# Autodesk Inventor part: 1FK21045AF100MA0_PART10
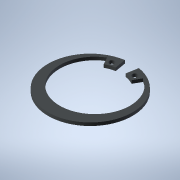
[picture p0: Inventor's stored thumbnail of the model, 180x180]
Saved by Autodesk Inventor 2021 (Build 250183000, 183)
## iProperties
Created: 2025-04
Part Number: 1FK21045AF100MA0_PART10
Material: Generic
Catalog Web Link: www.3dfindit.com
Description: -Servo synchronous motor
Document SubType Name: Modeling
Designer: psAdmin
Mass: 0.642463 g
Surface Area: 12.3927 cm^2
Volume: 0.642463 cm^3
Density: 1 g/cm^3
Appearance: PSOLRGB-212-217-219
Category: PARTsolutions
Title: 1FK21045AF100MA0_PART10
Author: Cadenas PARTsolutions
Comments: Servo synchronous motor
Sending System: PARTsolutions
Preprocessor: ST-DEVELOPER v19.3
PSOL_IDENT_0: {$CADENAS_DATA/23d-libs/siemens_ag/_cat_/52/6b/1fk21045af100ma0.prj},216 {VTYP=3D},{NB=1FK21045AF100
PSOL_IDENT_1: MA0_PART10},{LINA=1FK21045AF100MA0_PART10},{NN=1FK21045AF100MA0_PART10},{NOPRJ=TRUE},{DATE=19.08.202
PSOL_IDENT_2: 5 14:00:38},{GEOMDATE=30.07.2025 02:01:45},{VERSION=},{LINEID=10},{WBVAR=},{WBNUMERIC=}  {NB=1FK2104
PSOL_IDENT_3: 5AF100MA0_PART10},{LINA=1FK21045AF100MA0_PART10},{KT=DUMMY},{PREVIEW=../../../_pool_/cb/72/p_d211_xx
PSOL_IDENT_4: _00434j.png},{DESCSHORT=SIMOTICS S-1FK2 HD, SINAMICS S210 3AC 400V-480V, 2.4 Nm, 3000 rpm},{DESCLONG=
PSOL_IDENT_5: SIMOTICS S-1FK2 HD servo motor M0=2.4 Nm; PN = 0.75 kW at nN=3000 rpm (380-480 V); PN = 0.375 kW at
PSOL_IDENT_6: nN=1500 rpm (200-240 V); with holding brake; degree of protection IP64; cylindrical shaft D19x40mm;
PSOL_IDENT_7: absolute encoder 22-bit + 12-bit multiturn (encoder AM22DQC); with OCC interface; plug size M17, rot
PSOL_IDENT_8: atable; SIMOTICS S-1FK2 servomotorfor a wide range of uses in industrial environments. SIMOTICS S‑1F
PSOL_IDENT_9: K2 servomotors are compact synchronous motors with a high dynamic performance that set themselves ap
PSOL_IDENT_10: art as a result of their high power density, degree of protection and overload capability. The motor
PSOL_IDENT_11: s are available in two variants: as High Dynamic variant (highest dynamic performance as a result of
PSOL_IDENT_12: the low intrinsic moment of inertia for applications demanding a high dynamic performance with low
PSOL_IDENT_13: moved masses) - and as Compact variant (precise and stable closed-loop control for medium up to larg
PSOL_IDENT_14: e moved masses as a result of a medium intrinsic moment of inertia). SIMOTICSS‑1FK2 servomotors full
PSOL_IDENT_15: y exploit their strengths in a system with the SINAMICSS210 frequency converter and simple connectio
PSOL_IDENT_16: n using the one cable connection (OCC). Advantages include the short control and positioning times,
PSOL_IDENT_17: fast and precise correction of disturbing quantities as well as stable control with a high dynamic p
PSOL_IDENT_18: erformance. The servo motors can be configured to address a wide range of requirements. For example
PSOL_IDENT_19: with and without holding brake, IP64 or IP65 degree of protection, singleturn or multiturn absolute
PSOL_IDENT_20: encoders - to name just a few. Further, the servomotors are available in different shaft heights ext
PSOL_IDENT_21: ending from 20 to 100. A shaft sealing ring is available to achieve an IP65 degree of protection and
PSOL_IDENT_22: for subsequent mounting at the motor or as spare part. SIMOTICS - the optimum motor for each and ev
PSOL_IDENT_23: ery motion control application.},{INTNO=804766906411},{SUPPLIERALTNO=1FK2104-5AF10-0MA0},{MANUID=1FK
PSOL_IDENT_24: 21045AF100MA0},{MANUNAME=Siemens},{MANUTYPEDESC=Synchronous motor 1FK2-HD 2.4 NM},{AAU732=SIMOTICS},
PSOL_IDENT_25: {AAO057=S-1FK2},{AAU734=SIMOTICS S-1FK2 HD servo motor M0=2.4 Nm; PN = 0.75 kW at nN=3000 rpm (380-4
PSOL_IDENT_26: 80 V); PN = 0.375 kW at nN=1500 rpm (200-240 V); with holding brake; degree of protection IP64; cyli
PSOL_IDENT_27: ndrical shaft D19x40mm; absolute encoder 22-bit + 12-bit multiturn (encoder AM22DQC); with OCC inter
PSOL_IDENT_28: face; plug size M17, rotatable;},{AAW338=Synchronous motor 1FK2-HD 2.4 NM},{AAO742=SIMOTICS},{AAO663=
PSOL_IDENT_29: 4042948693070},{NOCUPEROU=1},{PRICEQUANTITY=1},{QUANTITYMIN=1},{QUANTITYINT=1},{CTN=85015100},{COO=D
PSOL_IDENT_30: E},{AAO676=1FK2104-5AF10-0MA0},{AAO677=Siemens AG},{ORDERUNIT=C62},{CONTENTUNIT=C62}
NB: 1FK21045AF100MA0_PART10
NT: Servo synchronous motor
NBSYN: $MANUID._PART10
LINA: 1FK21045AF100MA0_PART10
CATALOG: SIEMENS
PREVIEW: ../../../_pool_/cb/72/p_d211_xx_00434j.png
DESCSHORT: SIMOTICS S-1FK2 HD, SINAMICS S210 3AC 400V-480V, 2.4 Nm, 3000 rpm
DESCLONG: SIMOTICS S-1FK2 HD servo motor M0=2.4 Nm; PN = 0.75 kW at nN=3000 rpm (380-480 V); PN = 0.375 kW at nN=1500 rpm (200-240 V); with holding brake; degree of prote
INTNO: 804766906411
SUPPLIERALTNO: 1FK2104-5AF10-0MA0
MANUID: 1FK21045AF100MA0
MANUNAME: Siemens
MANUTYPEDESC: Synchronous motor 1FK2-HD 2.4 NM
AAU732: SIMOTICS
AAO057: S-1FK2
AAU734: SIMOTICS S-1FK2 HD servo motor M0=2.4 Nm; PN = 0.75 kW at nN=3000 rpm (380-480 V); PN = 0.375 kW at nN=1500 rpm (200-240 V); with holding brake; degree of prote
AAW338: Synchronous motor 1FK2-HD 2.4 NM
AAO742: SIMOTICS
AAO663: 4042948693070.0
NOCUPEROU: 1
PRICEQUANTITY: 1
QUANTITYMIN: 1
QUANTITYINT: 1
CTN: 85015100
COO: DE
ARTICLENO: 1FK21045AF100MA0_PART10
BOMINFO: 1FK21045AF100MA0_PART10
CREATOR: CADENAS GmbH
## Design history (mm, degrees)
feature "2025_04_17_15_34_52_0317"
body "Solid1"
